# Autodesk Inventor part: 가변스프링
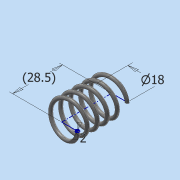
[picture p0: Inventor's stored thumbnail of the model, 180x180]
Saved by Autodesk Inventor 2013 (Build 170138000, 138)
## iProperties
Created: 2018-12
Part Number: 가변스프링
Material: 스테인레스 스틸
Document SubType Name: Modeling
Designer: dgall
Density: 8.08 g/cm^3
Mass: 7.0703 g
Surface Area: 17.7407 cm^2
Volume: 0.875038 cm^3
Author: dgall
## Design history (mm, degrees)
sketch "스케치1"
  geometry: L1 (0, 0)-(9, 0); L2 (0, 0)-(0, 28.5); L3 (0, 28.5)-(9, 28.5); C1 r 1 at (9, 0)
  constraints: 6 end point, 1 centre point, 1 coincident, 1 horizontal, 1 perpendicular, 1 vertical, 1 vertical alignment
  dimensions: "d0" = 18 diameter of L3.end L2; "d2" = 28.5 distance of L1.start L2.end (derived); "d3" = 2 diameter of C1
feature "코일1" pitch "d4" = 10; turns "d6" = 5; dims "d5" = 28.5 (= d2), "d7" = 0, angle "d8" = 90 deg, angle "d9" = 90 deg, "d10" = 0, "d11" = 0
node "작업 평면1"
feature "분할1"
feature "분할2"
node "솔리드1"
other parameters: "d12" = 0
